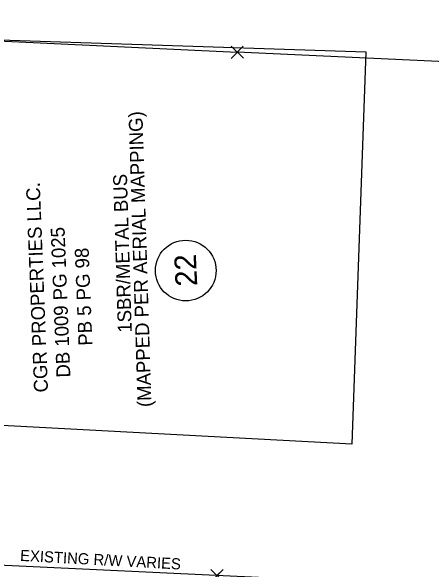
# Model space of a CAD drawing. Extents: x 1627482 to 1629573, y 760826 to 766301.
# Drawn here: x 1628615 to 1628736.2, y 763186.4 to 763347.5 of the extents above; entities that cross this region are included whole.
import ezdxf

# ---------------------------------------------------------------- set-up
doc = ezdxf.new("R2010")
doc.units = 0
for name, color, linetype in [('Default', 7, 'Continuous'), ('Exist Building', 7, 'Continuous'), ('Exist Building Text', 7, 'Continuous'), ('Exist Property Corner CELL', 7, 'Continuous'), ('Exist Property Deed Book Text', 7, 'Continuous'), ('Exist Property Line', 7, 'Continuous'), ('Exist Property Owner Number CELL', 7, 'Continuous'), ('Exist Property Owner Text', 7, 'Continuous'), ('Exist Right of Way Line', 7, 'Continuous'), ('Exist Right of Way Line Text', 7, 'Continuous')]:
    doc.layers.add(name, color=color, linetype=linetype)

# ---------------------------------------------------------------- blocks, each defined once
blk = doc.blocks.new('POINT_DISPLAY')
at = {"layer": 'Default'}
blk.add_line((0, 0), (0, 0), dxfattribs=at)
blk = doc.blocks.new('EXIST PROPERTY CORNER')
at = {"layer": 'Exist Property Corner CELL'}
blk.add_lwpolyline([(-3.81, 0), (3.81, 0), (0, 0), (0, 3.81), (0, -3.81)], dxfattribs=at)
blk.add_blockref('POINT_DISPLAY', (0, 0), dxfattribs=at)

msp = doc.modelspace()

# ---------------------------------------------------------------- linework, layer by layer
at = {"layer": 'Exist Building'}
msp.add_lwpolyline([(1628572.68, 763230.13), (1628576.46, 763340.39), (1628717.21, 763335.71), (1628713.19, 763222.61)], close=True, dxfattribs=at)
at = {"layer": 'Exist Property Line'}
for p in [(1628430.42, 763347.46), (1628896.11, 763325.61)]:
    msp.add_line(p, (1628680.14, 763335.62), dxfattribs=at)
at = {"layer": 'Exist Property Owner Number CELL'}
msp.add_circle((1628665.32, 763272.68), 8.75, dxfattribs=at)
at = {"layer": 'Exist Right of Way Line'}
msp.add_lwpolyline([(1628775.4, 763179.95), (1628434.73, 763196.09)], dxfattribs=at)

# ---------------------------------------------------------------- block references
at = {"layer": 'Exist Property Corner CELL', "xscale": 0.6561666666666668, "yscale": 0.6561666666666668, "rotation": 45.72460018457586}
for p in [(1628680.14, 763335.62), (1628674.31, 763184.74)]:
    msp.add_blockref('EXIST PROPERTY CORNER', p, dxfattribs=at)

# ---------------------------------------------------------------- texts
at = {"layer": 'Exist Building Text'}
for s, p in [('(MAPPED PER AERIAL MAPPING)', (1628655.46, 763233.39)), ('1SBR/METAL BUS', (1628649.78, 763254.83))]:
    msp.add_text(s, height=4, rotation=91.7713, dxfattribs=at).set_placement(p)
at = {"layer": 'Exist Property Deed Book Text'}
for s, p in [('DB 1009 PG 1025', (1628632.1, 763241.91)), ('PB 5 PG 98', (1628638.44, 763251.1))]:
    msp.add_text(s, height=4, rotation=92.2582, dxfattribs=at).set_placement(p)
at = {"layer": 'Exist Property Owner Number CELL'}
msp.add_text('22', height=6.25, rotation=92.6915, dxfattribs=at).set_placement((1628668.65, 763268.26))
at = {"layer": 'Exist Property Owner Text'}
msp.add_text('CGR PROPERTIES LLC.', height=4, rotation=92.2582, dxfattribs=at).set_placement((1628625.66, 763237.61))
at = {"layer": 'Exist Right of Way Line Text'}
msp.add_text('EXISTING R/W VARIES', height=3.2, rotation=356.9068, dxfattribs=at).set_placement((1628617.54, 763188.99))

doc.saveas('drawing.dxf')
